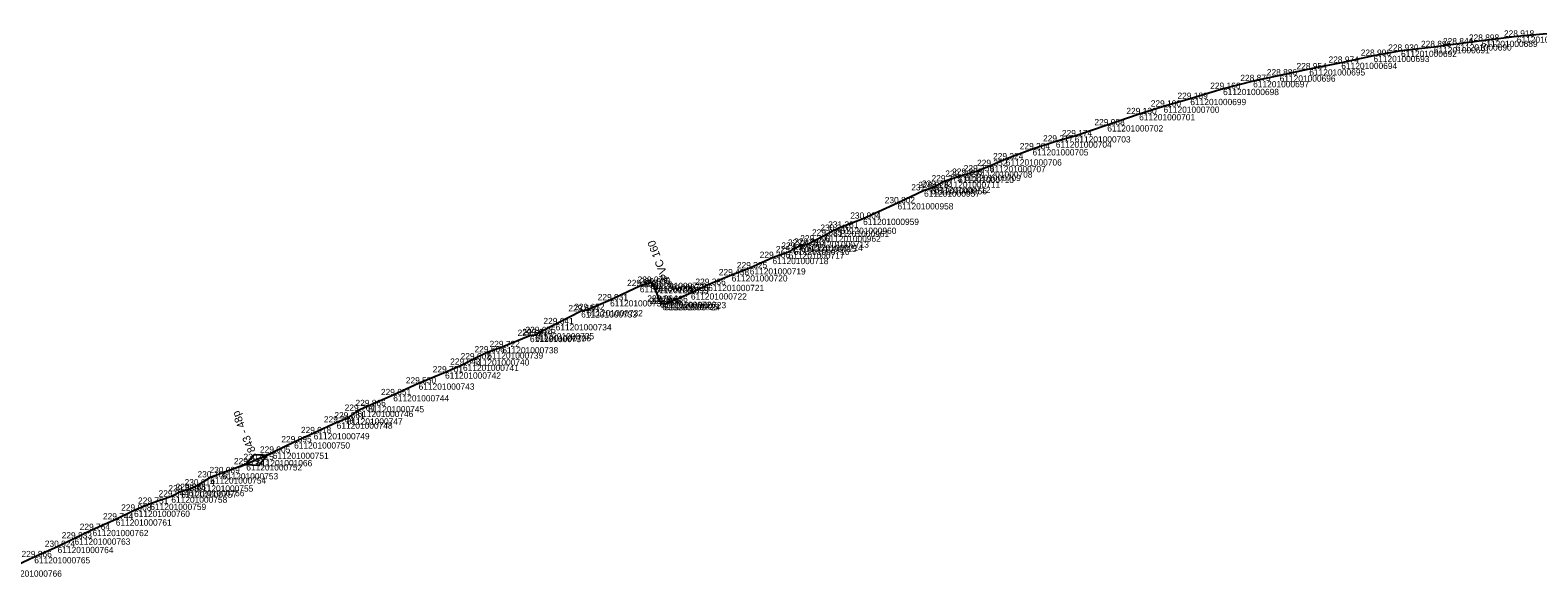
# Model space of a CAD drawing. Extents: x -771040 to -768909, y -1052366 to -1050115.
# Drawn here: x -770297.8 to -770008.9, y -1050222.5 to -1050117.8 of the extents above; entities that cross this region are included whole.
import ezdxf

# ---------------------------------------------------------------- set-up
doc = ezdxf.new("R2010")
doc.units = 0
for name, color, linetype in [('Vrstva 28', 7, 'Continuous'), ('Vrstva 35', 7, 'Continuous'), ('Vrstva 60', 7, 'Continuous'), ('Vrstva 61', 7, 'Continuous')]:
    doc.layers.add(name, color=color, linetype=linetype)

msp = doc.modelspace()

# ---------------------------------------------------------------- linework, layer by layer
at = {"layer": 'Vrstva 28'}
for p, q in [((-770251.21, -1050198.77), (-770257.65, -1050201.47)), ((-770256.58, -1050201.02), (-770254.88, -1050199.04)), ((-770254.88, -1050199.04), (-770252.29, -1050199.22)), ((-770252.29, -1050199.22), (-770253.98, -1050201.19)), ((-770253.98, -1050201.19), (-770256.58, -1050201.02))]:
    msp.add_line(p, q, dxfattribs=at)
for points in [[(-770006.4, -1050118.41), (-770012.92, -1050119.01), (-770019.65, -1050119.81), (-770024.62, -1050120.5), (-770028.82, -1050121.03), (-770035.11, -1050121.72), (-770040.38, -1050122.7), (-770046.55, -1050124.03), (-770052.68, -1050125.27), (-770058.36, -1050126.45), (-770063.44, -1050127.54), (-770069.21, -1050129.03), (-770075.48, -1050130.95), (-770080.61, -1050132.42), (-770085.28, -1050133.87), (-770091.39, -1050136), (-770097.63, -1050138.1), (-770101.25, -1050139.11), (-770105.71, -1050140.59), (-770110.82, -1050142.52), (-770113.89, -1050143.81), (-770116.43, -1050144.83), (-770118.67, -1050145.49), (-770119.98, -1050145.87), (-770122.62, -1050146.76), (-770124.46, -1050147.79)], [(-770124.46, -1050147.79), (-770125.15, -1050148.04), (-770126.5, -1050148.49), (-770131.58, -1050150.93), (-770138.18, -1050153.9), (-770142.51, -1050155.61), (-770143.91, -1050156.22)], [(-770143.91, -1050156.22), (-770145.5, -1050157.13), (-770147.77, -1050158.25), (-770148.95, -1050158.89), (-770150.13, -1050159.07), (-770151.49, -1050159.65), (-770152.44, -1050160.33), (-770155.53, -1050161.41), (-770159.89, -1050163.39), (-770163.36, -1050164.73), (-770167.85, -1050166.57), (-770171.16, -1050168.19), (-770175.13, -1050169.86), (-770176.29, -1050170.25)], [(-770178.93, -1050166.17), (-770180.95, -1050166.81), (-770186.66, -1050169.51), (-770191.08, -1050171.4), (-770192.19, -1050171.63), (-770197.08, -1050174.1), (-770200.42, -1050175.8), (-770201.02, -1050176.2), (-770202.01, -1050176.35), (-770207.3, -1050178.5), (-770210.18, -1050179.5), (-770212.84, -1050180.83), (-770214.84, -1050181.87), (-770218.28, -1050183.34), (-770223.34, -1050185.46), (-770228.2, -1050187.7), (-770232.99, -1050189.8), (-770235.06, -1050190.7), (-770237.12, -1050192.15), (-770239.04, -1050192.93), (-770243.44, -1050194.98), (-770247.19, -1050196.73), (-770251.28, -1050198.71), (-770254.43, -1050200.12), (-770256.36, -1050200.93), (-770260.96, -1050202.64), (-770263.26, -1050203.46), (-770265.73, -1050204.99), (-770267.43, -1050205.86), (-770268.84, -1050206.15), (-770270.72, -1050207.12), (-770274.75, -1050208.5), (-770277.87, -1050209.82), (-770281.37, -1050211.5), (-770285.82, -1050213.51), (-770289.28, -1050215.15), (-770292.51, -1050216.76), (-770296.98, -1050218.73), (-770302.4, -1050221.28)], [(-770176.29, -1050170.25), (-770176.65, -1050170.22), (-770177.07, -1050169.78), (-770178.13, -1050167), (-770178.47, -1050166.46), (-770178.93, -1050166.17)]]:
    msp.add_lwpolyline(points, dxfattribs=at)
at = {"layer": 'Vrstva 35'}
msp.add_lwpolyline([(-770176.29, -1050170.25), (-770176.65, -1050170.22), (-770177.07, -1050169.78), (-770178.13, -1050167), (-770178.47, -1050166.46), (-770178.93, -1050166.17)], dxfattribs=at)
at = {"layer": 'Vrstva 60'}
for p, q in [((-770012.92, -1050119.01), (-770012.92, -1050119.01)), ((-770035.11, -1050121.72), (-770035.11, -1050121.72)), ((-770028.82, -1050121.03), (-770028.82, -1050121.03)), ((-770024.62, -1050120.5), (-770024.62, -1050120.5)), ((-770019.65, -1050119.81), (-770019.65, -1050119.81)), ((-770046.55, -1050124.03), (-770046.55, -1050124.03)), ((-770040.38, -1050122.7), (-770040.38, -1050122.7)), ((-770063.44, -1050127.54), (-770063.44, -1050127.54)), ((-770058.36, -1050126.45), (-770058.36, -1050126.45)), ((-770052.68, -1050125.27), (-770052.68, -1050125.27)), ((-770075.48, -1050130.95), (-770075.48, -1050130.95)), ((-770069.21, -1050129.03), (-770069.21, -1050129.03)), ((-770085.28, -1050133.87), (-770085.28, -1050133.87)), ((-770080.61, -1050132.42), (-770080.61, -1050132.42)), ((-770091.39, -1050136), (-770091.39, -1050136)), ((-770101.25, -1050139.11), (-770101.25, -1050139.11)), ((-770097.63, -1050138.1), (-770097.63, -1050138.1)), ((-770110.82, -1050142.52), (-770110.82, -1050142.52)), ((-770105.71, -1050140.59), (-770105.71, -1050140.59)), ((-770116.43, -1050144.83), (-770116.43, -1050144.83)), ((-770113.89, -1050143.81), (-770113.89, -1050143.81)), ((-770125.15, -1050148.04), (-770125.15, -1050148.04)), ((-770124.46, -1050147.79), (-770124.46, -1050147.79)), ((-770122.62, -1050146.76), (-770122.62, -1050146.76)), ((-770119.98, -1050145.87), (-770119.98, -1050145.87)), ((-770118.67, -1050145.49), (-770118.67, -1050145.49)), ((-770131.58, -1050150.93), (-770131.58, -1050150.93)), ((-770126.5, -1050148.49), (-770126.5, -1050148.49)), ((-770138.18, -1050153.9), (-770138.18, -1050153.9)), ((-770143.91, -1050156.22), (-770143.91, -1050156.22)), ((-770142.51, -1050155.61), (-770142.51, -1050155.61)), ((-770151.49, -1050159.65), (-770151.49, -1050159.65)), ((-770150.13, -1050159.07), (-770150.13, -1050159.07)), ((-770148.95, -1050158.89), (-770148.95, -1050158.89)), ((-770147.77, -1050158.25), (-770147.77, -1050158.25)), ((-770145.5, -1050157.13), (-770145.5, -1050157.13)), ((-770155.53, -1050161.41), (-770155.53, -1050161.41)), ((-770152.44, -1050160.33), (-770152.44, -1050160.33)), ((-770163.36, -1050164.73), (-770163.36, -1050164.73)), ((-770159.89, -1050163.39), (-770159.89, -1050163.39)), ((-770180.95, -1050166.81), (-770180.95, -1050166.81)), ((-770178.93, -1050166.17), (-770178.93, -1050166.17)), ((-770178.47, -1050166.46), (-770178.47, -1050166.46)), ((-770178.13, -1050167), (-770178.13, -1050167)), ((-770171.16, -1050168.19), (-770171.16, -1050168.19)), ((-770167.85, -1050166.57), (-770167.85, -1050166.57)), ((-770191.08, -1050171.4), (-770191.08, -1050171.4)), ((-770186.66, -1050169.51), (-770186.66, -1050169.51)), ((-770177.07, -1050169.78), (-770177.07, -1050169.78)), ((-770176.65, -1050170.22), (-770176.65, -1050170.22)), ((-770176.29, -1050170.25), (-770176.29, -1050170.25)), ((-770175.13, -1050169.86), (-770175.13, -1050169.86)), ((-770197.08, -1050174.1), (-770197.08, -1050174.1)), ((-770192.19, -1050171.63), (-770192.19, -1050171.63)), ((-770202.01, -1050176.35), (-770202.01, -1050176.35)), ((-770201.02, -1050176.2), (-770201.02, -1050176.2)), ((-770200.42, -1050175.8), (-770200.42, -1050175.8)), ((-770210.18, -1050179.5), (-770210.18, -1050179.5)), ((-770207.3, -1050178.5), (-770207.3, -1050178.5)), ((-770214.84, -1050181.87), (-770214.84, -1050181.87)), ((-770212.84, -1050180.83), (-770212.84, -1050180.83)), ((-770223.34, -1050185.46), (-770223.34, -1050185.46)), ((-770218.28, -1050183.34), (-770218.28, -1050183.34)), ((-770228.2, -1050187.7), (-770228.2, -1050187.7)), ((-770235.06, -1050190.7), (-770235.06, -1050190.7)), ((-770232.99, -1050189.8), (-770232.99, -1050189.8)), ((-770239.04, -1050192.93), (-770239.04, -1050192.93)), ((-770237.12, -1050192.15), (-770237.12, -1050192.15)), ((-770247.19, -1050196.73), (-770247.19, -1050196.73)), ((-770243.44, -1050194.98), (-770243.44, -1050194.98)), ((-770254.43, -1050200.12), (-770254.43, -1050200.12)), ((-770251.28, -1050198.71), (-770251.28, -1050198.71)), ((-770260.96, -1050202.64), (-770260.96, -1050202.64)), ((-770256.36, -1050200.93), (-770256.36, -1050200.93)), ((-770267.43, -1050205.86), (-770267.43, -1050205.86)), ((-770265.73, -1050204.99), (-770265.73, -1050204.99)), ((-770263.26, -1050203.46), (-770263.26, -1050203.46)), ((-770274.75, -1050208.5), (-770274.75, -1050208.5)), ((-770270.72, -1050207.12), (-770270.72, -1050207.12)), ((-770268.84, -1050206.15), (-770268.84, -1050206.15)), ((-770281.37, -1050211.5), (-770281.37, -1050211.5)), ((-770277.87, -1050209.82), (-770277.87, -1050209.82)), ((-770285.82, -1050213.51), (-770285.82, -1050213.51)), ((-770292.51, -1050216.76), (-770292.51, -1050216.76)), ((-770289.28, -1050215.15), (-770289.28, -1050215.15)), ((-770296.98, -1050218.73), (-770296.98, -1050218.73))]:
    msp.add_line(p, q, dxfattribs=at)

# ---------------------------------------------------------------- texts
at = {"layer": 'Vrstva 28'}
msp.add_text('843 - 48p', height=1.5, rotation=112.7607, dxfattribs=at).set_placement((-770254.53, -1050198.36))
at = {"layer": 'Vrstva 35'}
msp.add_text('PVC 160', height=1.5, rotation=110.8407, dxfattribs=at).set_placement((-770175.3, -1050165.4))
at = {"layer": 'Vrstva 60'}
for s, p in [('611201000688', (-770012.92, -1050120.21)), ('611201000692', (-770035.11, -1050122.92)), ('611201000691', (-770028.82, -1050122.23)), ('611201000690', (-770024.62, -1050121.7)), ('611201000689', (-770019.65, -1050121.02)), ('611201000694', (-770046.55, -1050125.23)), ('611201000693', (-770040.38, -1050123.9)), ('611201000697', (-770063.44, -1050128.74)), ('611201000696', (-770058.36, -1050127.65)), ('611201000695', (-770052.68, -1050126.47)), ('611201000699', (-770075.48, -1050132.15)), ('611201000698', (-770069.21, -1050130.23)), ('611201000701', (-770085.28, -1050135.07)), ('611201000700', (-770080.61, -1050133.62)), ('611201000702', (-770091.39, -1050137.2)), ('611201000704', (-770101.25, -1050140.31)), ('611201000703', (-770097.63, -1050139.3)), ('611201000706', (-770110.82, -1050143.72)), ('611201000705', (-770105.71, -1050141.79)), ('611201000708', (-770116.43, -1050146.03)), ('611201000707', (-770113.89, -1050145.01)), ('611201000956', (-770125.15, -1050149.24)), ('611201000712', (-770124.46, -1050148.99)), ('611201000711', (-770122.62, -1050147.96)), ('611201000710', (-770119.98, -1050147.07)), ('611201000709', (-770118.67, -1050146.69)), ('611201000958', (-770131.58, -1050152.13)), ('611201000957', (-770126.5, -1050149.69)), ('611201000959', (-770138.18, -1050155.1)), ('611201000961', (-770143.91, -1050157.42)), ('611201000960', (-770142.51, -1050156.81)), ('611201000716', (-770151.49, -1050160.85)), ('611201000715', (-770150.13, -1050160.27)), ('611201000714', (-770148.95, -1050160.09)), ('611201000713', (-770147.77, -1050159.45)), ('611201000962', (-770145.5, -1050158.33)), ('611201000718', (-770155.53, -1050162.61)), ('611201000717', (-770152.44, -1050161.53)), ('611201000720', (-770163.36, -1050165.93)), ('611201000719', (-770159.89, -1050164.59)), ('611201000730', (-770180.95, -1050168.02)), ('611201000729', (-770178.93, -1050167.37)), ('611201000728', (-770178.47, -1050167.66)), ('611201000727', (-770178.13, -1050168.2)), ('611201000722', (-770171.16, -1050169.39)), ('611201000721', (-770167.85, -1050167.77)), ('611201000732', (-770191.08, -1050172.6)), ('611201000731', (-770186.66, -1050170.71)), ('611201000726', (-770177.07, -1050170.98)), ('611201000725', (-770176.65, -1050171.42)), ('611201000724', (-770176.29, -1050171.45)), ('611201000723', (-770175.13, -1050171.06)), ('611201000734', (-770197.08, -1050175.3)), ('611201000733', (-770192.19, -1050172.83)), ('611201000737', (-770202.01, -1050177.55)), ('611201000736', (-770201.02, -1050177.4)), ('611201000735', (-770200.42, -1050177)), ('611201000739', (-770210.18, -1050180.7)), ('611201000738', (-770207.3, -1050179.7)), ('611201000741', (-770214.84, -1050183.07)), ('611201000740', (-770212.84, -1050182.03)), ('611201000743', (-770223.34, -1050186.66)), ('611201000742', (-770218.28, -1050184.54)), ('611201000744', (-770228.2, -1050188.9)), ('611201000746', (-770235.06, -1050191.9)), ('611201000745', (-770232.99, -1050191)), ('611201000748', (-770239.04, -1050194.13)), ('611201000747', (-770237.12, -1050193.35)), ('611201000750', (-770247.19, -1050197.93)), ('611201000749', (-770243.44, -1050196.18)), ('611201001066', (-770254.43, -1050201.32)), ('611201000751', (-770251.28, -1050199.91)), ('611201000753', (-770260.96, -1050203.84)), ('611201000752', (-770256.36, -1050202.13)), ('611201000756', (-770267.43, -1050207.06)), ('611201000755', (-770265.73, -1050206.19)), ('611201000754', (-770263.26, -1050204.66)), ('611201000759', (-770274.75, -1050209.7)), ('611201000758', (-770270.72, -1050208.32)), ('611201000757', (-770268.84, -1050207.35)), ('611201000761', (-770281.37, -1050212.7)), ('611201000760', (-770277.87, -1050211.02)), ('611201000762', (-770285.82, -1050214.71)), ('611201000764', (-770292.51, -1050217.96)), ('611201000763', (-770289.28, -1050216.35)), ('611201000765', (-770296.98, -1050219.93)), ('611201000766', (-770302.4, -1050222.48))]:
    msp.add_text(s, height=1.2, dxfattribs=at).set_placement(p)
at = {"layer": 'Vrstva 61'}
for s, p in [('228.844', (-770027.07, -1050120.5)), ('228.898', (-770022.1, -1050119.81)), ('228.918', (-770015.38, -1050119.01)), ('228.996', (-770042.83, -1050122.7)), ('228.930', (-770037.56, -1050121.72)), ('228.896', (-770031.28, -1050121.03)), ('228.954', (-770055.13, -1050125.27)), ('228.974', (-770049, -1050124.03)), ('229.166', (-770071.66, -1050129.03)), ('228.875', (-770065.9, -1050127.54)), ('228.886', (-770060.82, -1050126.45)), ('229.189', (-770077.94, -1050130.95)), ('229.130', (-770087.73, -1050133.87)), ('229.100', (-770083.06, -1050132.42)), ('229.088', (-770093.85, -1050136)), ('229.284', (-770108.16, -1050140.59)), ('229.217', (-770103.7, -1050139.11)), ('229.174', (-770100.08, -1050138.1)), ('229.324', (-770113.27, -1050142.52)), ('229.282', (-770122.43, -1050145.87)), ('229.238', (-770121.12, -1050145.49)), ('229.359', (-770118.89, -1050144.83)), ('229.352', (-770116.34, -1050143.81)), ('231.292', (-770128.95, -1050148.49)), ('229.823', (-770127.61, -1050148.04)), ('229.772', (-770126.91, -1050147.79)), ('229.375', (-770125.07, -1050146.76)), ('230.802', (-770134.03, -1050150.93)), ('230.904', (-770140.63, -1050153.9)), ('229.635', (-770147.96, -1050157.13)), ('230.210', (-770146.36, -1050156.22)), ('231.281', (-770144.87, -1050155.61)), ('229.230', (-770154.89, -1050160.33)), ('229.401', (-770153.84, -1050159.65)), ('229.473', (-770152.58, -1050159.07)), ('229.313', (-770151.4, -1050158.89)), ('229.300', (-770150.22, -1050158.25)), ('229.325', (-770162.35, -1050163.39)), ('229.306', (-770157.98, -1050161.41)), ('229.652', (-770183.4, -1050166.81)), ('230.079', (-770181.38, -1050166.17)), ('229.988', (-770180.92, -1050166.46)), ('229.386', (-770170.3, -1050166.57)), ('229.438', (-770165.82, -1050164.73)), ('229.931', (-770189.02, -1050169.51)), ('229.179', (-770180.58, -1050167)), ('229.399', (-770173.62, -1050168.19)), ('229.684', (-770194.64, -1050171.63)), ('229.652', (-770193.53, -1050171.4)), ('229.064', (-770179.52, -1050169.78)), ('229.979', (-770179.1, -1050170.22)), ('229.956', (-770178.74, -1050170.25)), ('229.636', (-770177.58, -1050169.86)), ('229.641', (-770199.43, -1050174.1)), ('229.621', (-770204.37, -1050176.35)), ('229.634', (-770203.47, -1050176.2)), ('229.675', (-770202.87, -1050175.8)), ('229.602', (-770215.29, -1050180.83)), ('229.606', (-770212.63, -1050179.5)), ('229.722', (-770209.75, -1050178.5)), ('229.701', (-770220.64, -1050183.34)), ('229.643', (-770217.29, -1050181.87)), ('229.550', (-770225.79, -1050185.46)), ('229.866', (-770235.44, -1050189.8)), ('229.651', (-770230.56, -1050187.7)), ('229.861', (-770239.48, -1050192.15)), ('229.764', (-770237.51, -1050190.7)), ('229.918', (-770245.89, -1050194.98)), ('229.784', (-770241.49, -1050192.93)), ('229.895', (-770249.64, -1050196.73)), ('229.791', (-770258.72, -1050200.93)), ('230.015', (-770256.89, -1050200.12)), ('229.905', (-770253.73, -1050198.71)), ('230.105', (-770265.71, -1050203.46)), ('230.089', (-770263.41, -1050202.64)), ('229.844', (-770273.17, -1050207.12)), ('229.889', (-770271.29, -1050206.15)), ('229.888', (-770269.89, -1050205.86)), ('230.014', (-770268.19, -1050204.99)), ('229.908', (-770280.33, -1050209.82)), ('229.751', (-770277.1, -1050208.5)), ('229.744', (-770283.82, -1050211.5)), ('229.833', (-770291.73, -1050215.15)), ('229.764', (-770288.27, -1050213.51)), ('229.866', (-770299.43, -1050218.73)), ('230.024', (-770294.96, -1050216.76))]:
    msp.add_text(s, height=1.2, dxfattribs=at).set_placement(p)

doc.saveas('drawing.dxf')
